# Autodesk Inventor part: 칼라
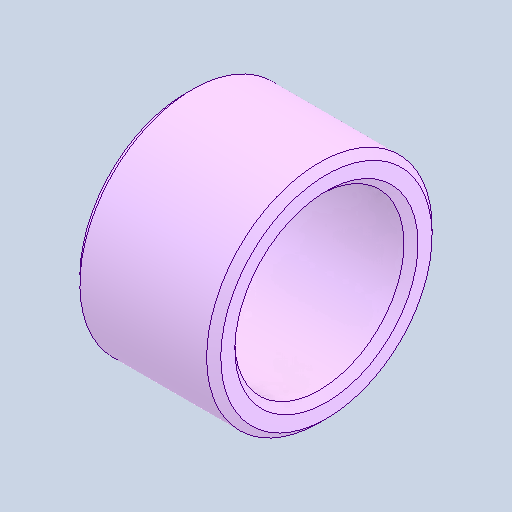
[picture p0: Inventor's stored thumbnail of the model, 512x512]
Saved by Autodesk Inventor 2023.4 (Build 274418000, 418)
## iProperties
Created: 2024-05
Part Number: 칼라
Material: 강철, 합금
Document SubType Name: Modeling
Designer: edu-40
Density: 7.73 g/cm^3
Appearance: 기본값
Author: jhkim
Sending System: Autodesk Inventor 2025
Preprocessor: ST-DEVELOPER v20
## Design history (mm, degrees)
feature "솔리드1"
node "솔리드2"
